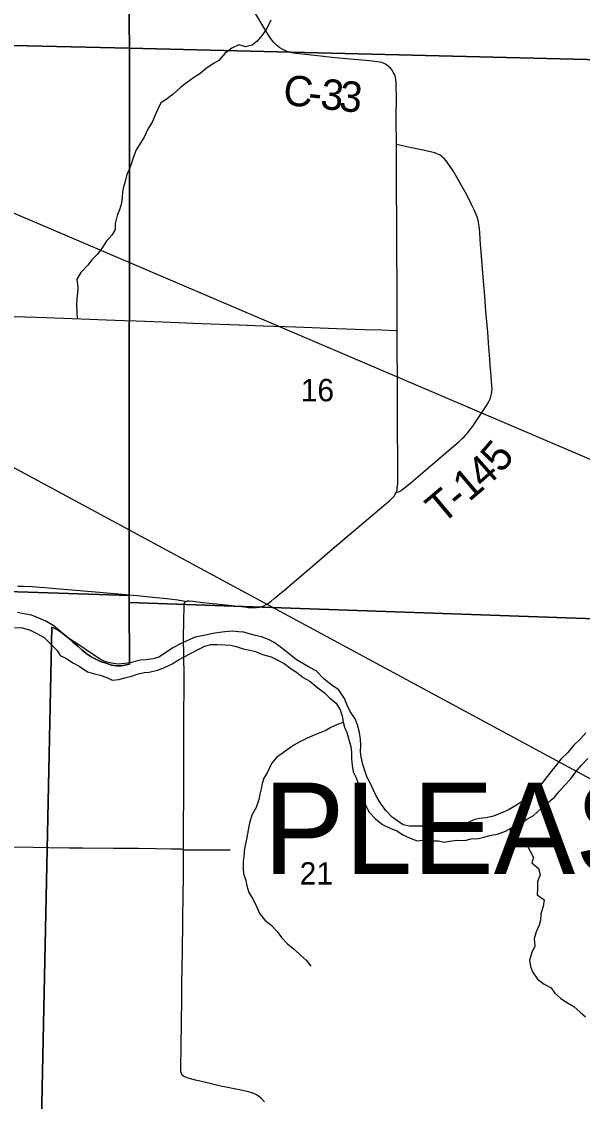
# Model space of a CAD drawing. Extents: x 0 to 34, y 0 to 22.
# Drawn here: x 4.718 to 5.242, y 18.765 to 19.773 of the extents above; entities that cross this region are included whole.
import ezdxf

# ---------------------------------------------------------------- set-up
doc = ezdxf.new("R2010")
doc.units = 0
for name, color, linetype in [('GM_X_Corporation', 7, 'Continuous'), ('GM_X_County_Road', 7, 'Continuous'), ('GM_X_County_Road_Text', 7, 'Continuous'), ('GM_X_Major_River', 7, 'Continuous'), ('GM_X_Minor_River', 7, 'Continuous'), ('GM_X_Section_Text', 7, 'Continuous'), ('GM_X_Township_Road', 7, 'Continuous'), ('GM_X_Township_Road_Text', 7, 'Continuous'), ('GM_X_Township_Text', 7, 'Continuous'), ('SH_Text', 7, 'Continuous')]:
    doc.layers.add(name, color=color, linetype=linetype)

msp = doc.modelspace()

# ---------------------------------------------------------------- linework, layer by layer
at = {"layer": 'GM_X_Corporation'}
for points in [[(4.8123, 20.246), (4.8186, 19.7484), (4.3141, 19.7601), (4.3097, 20.258)], [(5.2745, 20.2518), (5.2825, 19.7741), (5.2855, 19.7694), (5.2893, 19.764), (5.2986, 19.7516), (5.3057, 19.7445), (5.3092, 19.7364), (4.8186, 19.7484), (4.8123, 20.246)], [(4.8186, 19.7484), (4.8183, 19.2373), (4.3173, 19.2536), (4.3141, 19.7601)], [(4.3173, 19.2536), (4.8183, 19.2373), (4.8183, 19.2305), (4.8184, 19.1729), (4.8111, 19.1716), (4.8064, 19.1716), (4.8016, 19.172), (4.7978, 19.1736), (4.7913, 19.1754), (4.7827, 19.18), (4.7791, 19.1822), (4.7739, 19.1864), (4.7702, 19.1898), (4.7655, 19.1936), (4.7609, 19.1979), (4.7551, 19.2027), (4.7518, 19.2049), (4.7489, 19.2062), (4.7461, 19.2076), (4.7363, 18.7476), (4.561, 18.7477), (4.545, 18.7213), (4.3048, 18.7327)]]:
    msp.add_lwpolyline(points, close=True, dxfattribs=at)
for points in [[(5.2804, 19.2145), (4.8183, 19.2305), (4.8183, 19.2373), (4.8186, 19.7484), (5.3092, 19.7364)], [(4.7363, 18.7476), (4.7461, 19.2076), (4.7489, 19.2062), (4.7518, 19.2049), (4.7551, 19.2027), (4.7609, 19.1979), (4.7655, 19.1936), (4.7702, 19.1898), (4.7739, 19.1864), (4.7791, 19.1822), (4.7827, 19.18), (4.7913, 19.1754), (4.7978, 19.1736), (4.8016, 19.172), (4.8064, 19.1716), (4.8111, 19.1716), (4.8184, 19.1729), (4.8183, 19.2305), (5.2804, 19.2145)]]:
    msp.add_lwpolyline(points, dxfattribs=at)
at = {"layer": 'GM_X_County_Road'}
for points in [[(5.068, 19.6584), (5.0678, 19.6816), (5.0682, 19.7042), (5.0679, 19.7112), (5.0678, 19.7163), (5.0674, 19.7193), (5.0671, 19.7211), (5.0667, 19.7228), (5.0659, 19.7245), (5.0651, 19.7262), (5.0639, 19.728), (5.0624, 19.7299), (5.0604, 19.7317), (5.0591, 19.7327), (5.0578, 19.7336), (5.0561, 19.7344), (5.0542, 19.735), (5.0522, 19.7355), (5.0504, 19.7358), (5.0458, 19.7363), (5.0356, 19.7372), (5.0108, 19.7396), (4.9944, 19.7413), (4.9746, 19.7435), (4.9715, 19.7439), (4.9691, 19.7445), (4.9669, 19.7451), (4.9653, 19.7457), (4.9632, 19.7466), (4.9612, 19.7476), (4.9592, 19.7489), (4.9575, 19.7501), (4.9559, 19.7514), (4.9545, 19.7527), (4.9532, 19.7541), (4.9503, 19.7578), (4.9468, 19.763), (4.9353, 19.7825)], [(5.0687, 19.4848), (5.0686, 19.5085), (5.0684, 19.5784), (5.0682, 19.625), (5.068, 19.6584)], [(5.0679, 19.3335), (5.0682, 19.3342), (5.0686, 19.3357), (5.0688, 19.3373), (5.0692, 19.3415), (5.0692, 19.3512), (5.069, 19.4053), (5.0689, 19.4367), (5.0687, 19.4702), (5.0687, 19.4848)], [(4.8709, 19.2314), (4.8718, 19.2319), (4.8722, 19.232), (4.8727, 19.2321), (4.8744, 19.2321), (4.8776, 19.2319), (4.8867, 19.2307), (4.8998, 19.2293), (4.9197, 19.2271), (4.9262, 19.2265), (4.9299, 19.2261), (4.9339, 19.2258), (4.9372, 19.2259), (4.94, 19.2262), (4.942, 19.2267), (4.944, 19.2274), (4.9464, 19.2287), (4.9485, 19.23), (4.951, 19.2319), (4.9538, 19.2342), (4.964, 19.2429), (4.9854, 19.261), (4.9897, 19.2646), (5.0081, 19.2804), (5.0379, 19.3057), (5.0562, 19.3211), (5.0617, 19.3257), (5.0645, 19.3285), (5.0661, 19.3304), (5.067, 19.3319), (5.0678, 19.3332), (5.0679, 19.3335)], [(4.8692, 19.0993), (4.8692, 19.1149), (4.8695, 19.1627), (4.8691, 19.1978), (4.8695, 19.228), (4.8696, 19.2289), (4.8697, 19.2296), (4.8699, 19.2301), (4.8701, 19.2306), (4.8705, 19.231), (4.8709, 19.2314)], [(4.8689, 19), (4.8689, 19.0139), (4.8692, 19.0583), (4.8692, 19.0993)], [(4.9447, 18.7642), (4.942, 18.7671), (4.9394, 18.7692), (4.9374, 18.7706), (4.9349, 18.7718), (4.9318, 18.773), (4.9282, 18.7739), (4.9215, 18.7753), (4.9163, 18.7763), (4.9104, 18.7774), (4.9053, 18.7786), (4.9, 18.7797), (4.891, 18.7818), (4.8801, 18.7844), (4.8735, 18.7861), (4.8708, 18.7871), (4.8691, 18.7881), (4.8679, 18.7892), (4.867, 18.7906), (4.8665, 18.7925), (4.8664, 18.7954), (4.8672, 18.8377), (4.8674, 18.8607), (4.8676, 18.8746), (4.8681, 18.9048), (4.8687, 18.9598), (4.8689, 18.9713), (4.8689, 19)]]:
    msp.add_lwpolyline(points, dxfattribs=at)
at = {"layer": 'GM_X_Major_River'}
for points in [[(5.2282, 19.0906), (5.2216, 19.0844), (5.2176, 19.0791), (5.2137, 19.074), (5.2088, 19.068), (5.2038, 19.0615), (5.1979, 19.0549), (5.1924, 19.0491), (5.1859, 19.0449), (5.1802, 19.0412), (5.1728, 19.037), (5.1656, 19.0339), (5.1587, 19.031), (5.1519, 19.0294), (5.1456, 19.0288), (5.1405, 19.0275), (5.1358, 19.0255), (5.1291, 19.0223), (5.1234, 19.0204), (5.117, 19.0193), (5.1104, 19.0196), (5.1037, 19.0217), (5.092, 19.0218), (5.0854, 19.0216), (5.0804, 19.0216), (5.0744, 19.0228), (5.0693, 19.0263), (5.064, 19.0301), (5.058, 19.0362), (5.0531, 19.0433), (5.0492, 19.0499), (5.0467, 19.0554), (5.0441, 19.061), (5.0408, 19.0672), (5.0389, 19.0726), (5.0365, 19.0792), (5.035, 19.0864), (5.0343, 19.0912), (5.0347, 19.0971), (5.0345, 19.103), (5.0336, 19.1092), (5.0318, 19.1163), (5.0296, 19.1218), (5.0247, 19.1287), (5.0219, 19.1346), (5.0194, 19.141), (5.014, 19.1492), (5.0082, 19.1527), (5.0001, 19.1594), (4.9931, 19.1668), (4.9865, 19.1703), (4.9806, 19.1735), (4.9746, 19.177), (4.968, 19.1825), (4.9606, 19.1883), (4.9537, 19.1932), (4.9486, 19.1959), (4.942, 19.1986), (4.9363, 19.1998), (4.9304, 19.2015), (4.9255, 19.2029), (4.9204, 19.2033), (4.9149, 19.2037), (4.9075, 19.2032), (4.9026, 19.2025), (4.8967, 19.2017), (4.8895, 19.2001), (4.8846, 19.1991), (4.8798, 19.1982), (4.8722, 19.1947), (4.8667, 19.1922), (4.8591, 19.1883), (4.853, 19.1841), (4.846, 19.1796), (4.8407, 19.1781), (4.8342, 19.177), (4.8289, 19.1767), (4.824, 19.1756), (4.8193, 19.1741), (4.8143, 19.1736), (4.8079, 19.173), (4.8018, 19.1738), (4.7965, 19.1752), (4.7914, 19.1775), (4.7856, 19.1813), (4.7792, 19.1855), (4.7741, 19.1892), (4.7669, 19.194), (4.7599, 19.1982), (4.7545, 19.2033), (4.7477, 19.2087), (4.7405, 19.2133), (4.7339, 19.216), (4.7271, 19.2189), (4.7199, 19.2201), (4.7139, 19.2212)], [(4.7111, 19.2072), (4.7181, 19.2068), (4.7251, 19.205), (4.7321, 19.2018), (4.7387, 19.1979), (4.7453, 19.1914), (4.751, 19.1859), (4.7538, 19.1811), (4.7598, 19.1782), (4.7655, 19.1744), (4.7715, 19.171), (4.7792, 19.166), (4.7857, 19.164), (4.791, 19.1627), (4.7974, 19.1607), (4.8023, 19.1581), (4.8087, 19.1588), (4.8142, 19.1601), (4.8205, 19.1619), (4.8256, 19.1636), (4.8323, 19.1651), (4.837, 19.1656), (4.8446, 19.1675), (4.8507, 19.1697), (4.8585, 19.1733), (4.8645, 19.1772), (4.8695, 19.1799), (4.8761, 19.1834), (4.8828, 19.1866), (4.8889, 19.1898), (4.8942, 19.1913), (4.9004, 19.1915), (4.908, 19.1912), (4.9133, 19.1908), (4.9184, 19.1895), (4.9248, 19.1873), (4.9311, 19.186), (4.9364, 19.1848), (4.943, 19.1821), (4.9509, 19.18), (4.956, 19.1775), (4.9632, 19.1736), (4.9696, 19.1688), (4.9745, 19.1654), (4.9809, 19.1606), (4.9872, 19.157), (4.9945, 19.151), (5.0007, 19.1461), (5.0058, 19.1411), (5.0118, 19.1365), (5.0154, 19.1302), (5.0173, 19.1247), (5.0182, 19.1188), (5.0195, 19.1141), (5.0217, 19.1093), (5.0236, 19.1025), (5.0254, 19.096), (5.0259, 19.0905), (5.0261, 19.0846), (5.0266, 19.0783), (5.0277, 19.0723), (5.0302, 19.0673), (5.0322, 19.0618), (5.0337, 19.057), (5.0357, 19.0517), (5.0376, 19.0464), (5.0395, 19.0407), (5.0425, 19.0348), (5.0485, 19.0285), (5.0549, 19.0233), (5.0622, 19.0197), (5.0689, 19.017), (5.0741, 19.0135), (5.0809, 19.0106), (5.0874, 19.0081), (5.0951, 19.0088), (5.1001, 19.0079), (5.1074, 19.008), (5.1124, 19.0068), (5.1175, 19.0078), (5.1245, 19.0085), (5.1321, 19.0084), (5.1379, 19.0099), (5.1446, 19.0101), (5.1497, 19.0114), (5.1567, 19.0132), (5.1624, 19.0143), (5.17, 19.0171), (5.1761, 19.0203), (5.1827, 19.0235), (5.1896, 19.028), (5.1962, 19.0316), (5.2029, 19.038), (5.2088, 19.0433), (5.2157, 19.0489), (5.2197, 19.0538), (5.2246, 19.0591), (5.2307, 19.0657), (5.2357, 19.0724), (5.241, 19.0788)], [(5.245, 19.1089), (5.2401, 19.1031), (5.2334, 19.097), (5.2282, 19.0906)], [(5.241, 19.0788), (5.2469, 19.0848)]]:
    msp.add_lwpolyline(points, dxfattribs=at)
at = {"layer": 'GM_X_Minor_River'}
for points in [[(4.9507, 19.7746), (4.9468, 19.767), (4.9424, 19.7607), (4.9379, 19.7551), (4.9331, 19.7513), (4.927, 19.7498), (4.9206, 19.7516), (4.9141, 19.7486), (4.9075, 19.7435), (4.9019, 19.7371), (4.8972, 19.7342), (4.8903, 19.7295), (4.8843, 19.7244), (4.8784, 19.7207), (4.8707, 19.7152), (4.866, 19.7113), (4.8595, 19.7056), (4.8527, 19.7005), (4.8477, 19.6975), (4.8448, 19.6909), (4.8422, 19.6854), (4.8397, 19.6795), (4.836, 19.6735), (4.8324, 19.6653), (4.8291, 19.6604), (4.8249, 19.6536), (4.8222, 19.647), (4.8205, 19.6411), (4.8184, 19.6356), (4.8161, 19.6305), (4.8145, 19.624), (4.8129, 19.6189), (4.812, 19.6142), (4.8117, 19.6091), (4.811, 19.6038), (4.8092, 19.5973), (4.8071, 19.592), (4.8053, 19.5848), (4.8051, 19.5791), (4.8019, 19.5738), (4.7967, 19.5678), (4.7935, 19.5629), (4.7887, 19.556), (4.7832, 19.5508), (4.7797, 19.5458), (4.7732, 19.5389), (4.7692, 19.5328), (4.7703, 19.525), (4.7699, 19.5197), (4.7693, 19.515), (4.7689, 19.5085), (4.7692, 19.5017), (4.7697, 19.4954)], [(5.0182, 19.1186), (5.013, 19.1166), (5.0068, 19.1138), (5.002, 19.1111), (4.9973, 19.1093), (4.991, 19.1068), (4.9846, 19.104), (4.9777, 19.1005), (4.9722, 19.0973), (4.9659, 19.0931), (4.9612, 19.0894), (4.9562, 19.086), (4.9514, 19.0803), (4.9472, 19.0716), (4.9442, 19.0665), (4.9424, 19.0616), (4.9416, 19.0566), (4.9405, 19.0515), (4.9393, 19.0466), (4.9368, 19.0392), (4.933, 19.0318), (4.9306, 19.0246), (4.9299, 19.0197), (4.9289, 19.0146), (4.9277, 19.0079), (4.9259, 19.0009), (4.9255, 18.9937), (4.9249, 18.9886), (4.9249, 18.9821), (4.9252, 18.9774), (4.9273, 18.9709), (4.9282, 18.966), (4.9302, 18.9597), (4.934, 18.9532), (4.9372, 18.9467), (4.9403, 18.9399), (4.945, 18.9338), (4.9507, 18.9294), (4.9565, 18.9233), (4.9606, 18.9176), (4.9661, 18.9118), (4.9727, 18.9063), (4.9783, 18.9011), (4.9838, 18.8965), (4.9879, 18.8908)], [(5.174, 19.0192), (5.1747, 19.0148), (5.1794, 19.0095), (5.1845, 19.0079), (5.19, 19.0041), (5.1926, 18.9988), (5.196, 18.9923), (5.1946, 18.9874), (5.2008, 18.9822), (5.2025, 18.9761), (5.1998, 18.9699), (5.2, 18.9634), (5.1996, 18.9575), (5.206, 18.9529), (5.2052, 18.9465), (5.2029, 18.9399), (5.2026, 18.934), (5.2013, 18.9292), (5.1986, 18.923), (5.1968, 18.9164), (5.1975, 18.9097), (5.1947, 18.9035), (5.1925, 18.8965), (5.1934, 18.8906), (5.1953, 18.8856), (5.1998, 18.8786), (5.206, 18.8742), (5.2128, 18.8707), (5.216, 18.8656), (5.2217, 18.8608), (5.2271, 18.8573), (5.2337, 18.8533), (5.2396, 18.8478), (5.2447, 18.8436)]]:
    msp.add_lwpolyline(points, dxfattribs=at)
at = {"layer": 'GM_X_Township_Road'}
for points in [[(5.0679, 19.3335), (5.0701, 19.3341), (5.0708, 19.3344), (5.0714, 19.3346), (5.0721, 19.335), (5.0727, 19.3355), (5.0817, 19.3428), (5.1014, 19.3595), (5.1209, 19.3759), (5.1265, 19.3808), (5.1296, 19.3838), (5.1313, 19.3855), (5.1328, 19.3872), (5.134, 19.3885), (5.135, 19.3898), (5.1373, 19.3927), (5.1394, 19.3955), (5.1431, 19.4008), (5.1462, 19.4055), (5.15, 19.4112), (5.1525, 19.4151), (5.1544, 19.4183), (5.1556, 19.4209), (5.1564, 19.4232), (5.157, 19.4256), (5.1573, 19.4278), (5.1574, 19.4302), (5.1573, 19.433), (5.1569, 19.4374), (5.1562, 19.446), (5.1557, 19.4516), (5.1552, 19.4581), (5.1543, 19.4689), (5.1533, 19.4831), (5.1521, 19.4961), (5.1515, 19.5029), (5.1506, 19.5168), (5.1492, 19.5345), (5.1475, 19.5541), (5.1465, 19.5651), (5.1459, 19.5761), (5.1456, 19.5793), (5.1453, 19.5822), (5.1448, 19.5859), (5.1442, 19.5886), (5.1434, 19.591), (5.1427, 19.593), (5.1408, 19.5973), (5.1389, 19.6012), (5.138, 19.6032), (5.1337, 19.6115), (5.1292, 19.6196), (5.1247, 19.6274), (5.121, 19.6339), (5.1182, 19.6379), (5.1161, 19.6409), (5.1144, 19.6433), (5.1126, 19.6453), (5.1112, 19.6466), (5.1097, 19.6479), (5.1082, 19.6488), (5.1066, 19.6496), (5.1053, 19.6502), (5.1038, 19.6507), (5.1012, 19.6514), (5.0931, 19.6531), (5.082, 19.6555), (5.0708, 19.6578), (5.068, 19.6584)], [(4.7109, 19.4977), (4.7211, 19.4974), (4.7407, 19.4968), (4.765, 19.496), (4.7814, 19.4953), (4.7966, 19.4948), (4.8137, 19.4942), (4.8249, 19.4937), (4.8491, 19.4928), (4.8858, 19.4914), (4.9209, 19.4901), (4.9435, 19.4891), (4.9737, 19.488), (5.0122, 19.4866), (5.0383, 19.4856), (5.0541, 19.4852), (5.0675, 19.4848), (5.0687, 19.4848)], [(4.7143, 19.2458), (4.7199, 19.2458), (4.7277, 19.2455), (4.7348, 19.2449), (4.7393, 19.2446), (4.7572, 19.2431), (4.7904, 19.2404), (4.8182, 19.2378), (4.8256, 19.2371), (4.8313, 19.2365), (4.8371, 19.236), (4.8435, 19.2353), (4.8536, 19.2342), (4.8638, 19.233), (4.8647, 19.2329), (4.8673, 19.2324), (4.8688, 19.2321), (4.8699, 19.2318), (4.8709, 19.2314)], [(4.7037, 19.0025), (4.7286, 19.0021), (4.7432, 19.0017), (4.7622, 19.0014), (4.7749, 19.0013), (4.8035, 19.0011), (4.8156, 19.0011), (4.8271, 19.001), (4.843, 19.0008), (4.8576, 19.0006), (4.8655, 19.0005), (4.8664, 19.0004), (4.8674, 19.0002), (4.8689, 19)], [(4.8689, 19), (4.8698, 18.9997), (4.8707, 18.9996), (4.8719, 18.9995), (4.8765, 18.9995), (4.8867, 18.9995), (4.8954, 18.9995), (4.905, 18.9995), (4.9127, 18.9995)]]:
    msp.add_lwpolyline(points, dxfattribs=at)
at = {"layer": 'SH_Text'}
msp.add_lwpolyline([(9.297, 16.882), (2.5966, 20.4971), (9.297, 17.6363)], close=True, dxfattribs=at)

# ---------------------------------------------------------------- texts
at = {"layer": 'GM_X_County_Road_Text'}
for s, rotation, p in [('C', 354.0335, (4.9613, 19.6957)), ('3', 354.0357, (4.9962, 19.692)), ('3', 354.0253, (5.0136, 19.6902)), ('-', 354.0469, (4.9846, 19.6933))]:
    msp.add_text(s, height=0.0284, rotation=rotation, dxfattribs=at).set_placement(p)
at = {"layer": 'GM_X_Section_Text'}
for s, p in [('16', (4.9786, 19.4186)), ('21', (4.9776, 18.9671))]:
    msp.add_text(s, height=0.02093, rotation=0, dxfattribs=at).set_placement(p)
at = {"layer": 'GM_X_Township_Road_Text'}
for s, rotation, p in [('5', 49.4608, (5.1658, 19.3505)), ('4', 41.3665, (5.1496, 19.3358)), ('1', 40.3633, (5.1359, 19.3241)), ('T', 40.1244, (5.1106, 19.3028)), ('-', 40.1657, (5.1269, 19.3165))]:
    msp.add_text(s, height=0.0284, rotation=rotation, dxfattribs=at).set_placement(p)
at = {"layer": 'GM_X_Township_Text'}
msp.add_text('PLEASANT', height=0.08523, rotation=0, dxfattribs=at).set_placement((4.9436, 18.9771))

doc.saveas('drawing.dxf')
